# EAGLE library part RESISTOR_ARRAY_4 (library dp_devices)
4 Resistor Array 0603
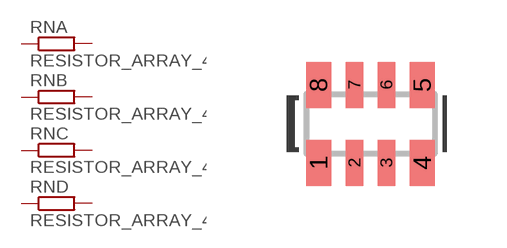
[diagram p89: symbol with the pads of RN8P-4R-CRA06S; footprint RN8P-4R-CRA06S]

Designator prefix RN; gates B=RESISTOR C=RESISTOR D=RESISTOR A=RESISTOR

## RESISTOR_ARRAY_4  [RN8P-4R-CRA06S]
1  A:1  pas
2  B:1  pas
3  C:1  pas
4  D:1  pas
5  D:2  pas
6  C:2  pas
7  B:2  pas
8  A:2  pas

## Footprint RN8P-4R-CRA06S (pad centres in mm)
smd 0.63 x 1.15: 1 -1.295,-0.975; 4 1.295,-0.975; 5 1.295,0.975; 8 -1.295,0.975
smd 0.44 x 1.15: 2 -0.4,-0.975; 3 0.4,-0.975; 6 0.4,0.975; 7 -0.4,0.975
